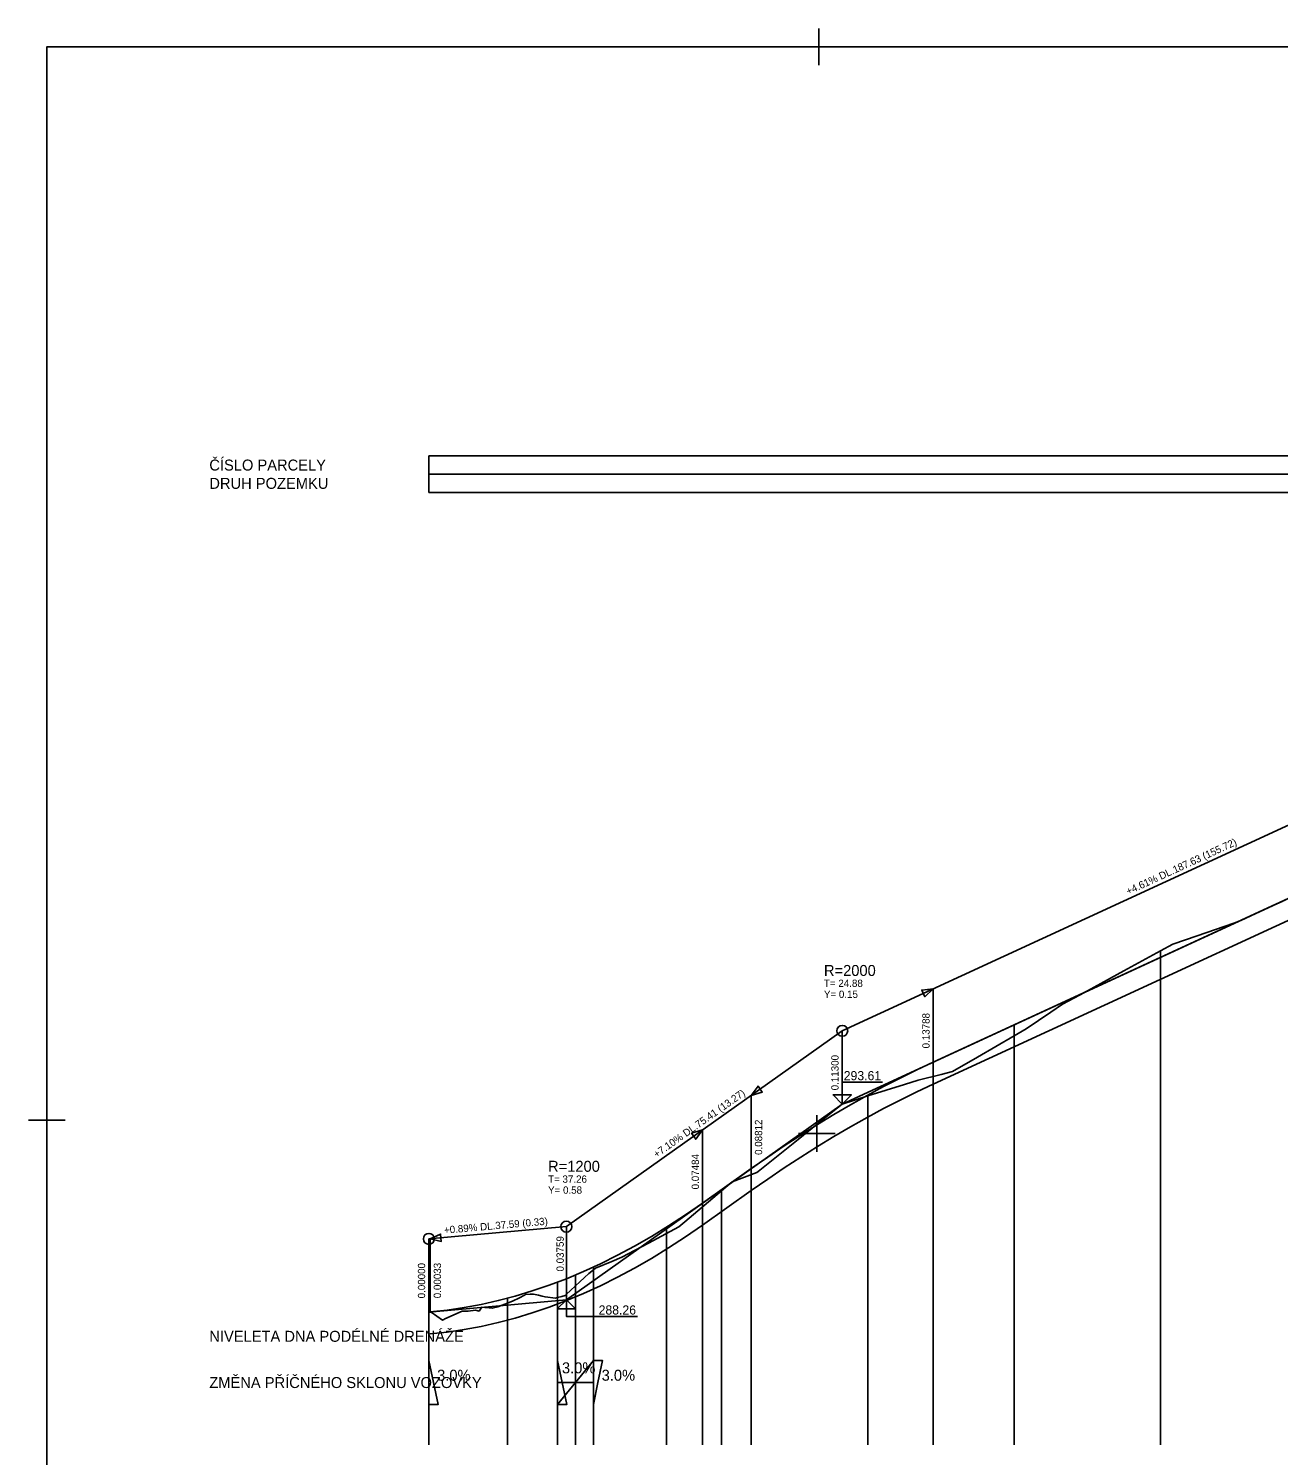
# Model space of a CAD drawing. Extents: x -39 to 1232, y -119 to 485.
# Drawn here: x -39.4 to 302.2, y 95.1 to 485.1 of the extents above; entities that cross this region are included whole.
import ezdxf

# ---------------------------------------------------------------- set-up
doc = ezdxf.new("R2010")
doc.units = 0
for name, color, linetype in [('KOTA', 7, 'Continuous'), ('NOVY_STAV', 7, 'Continuous'), ('NS_OBLOUK', 7, 'Continuous'), ('PRIKOPY', 7, 'Continuous'), ('ramecek', 7, 'Continuous'), ('REZY_PO', 7, 'Continuous'), ('SESTAVY_REZU_PO', 7, 'Continuous'), ('SKLONOVE_POMERY', 7, 'Continuous'), ('SKLONOVE_POMERY_PROPOJENI', 7, 'Continuous'), ('SVK_STAT', 7, 'Continuous'), ('TABULKY', 7, 'Continuous')]:
    doc.layers.add(name, color=color, linetype=linetype)

msp = doc.modelspace()

# ---------------------------------------------------------------- linework, layer by layer
for p, q in [((176.58, 485.08), (176.58, 475.08)), ((176.58, 485.08), (176.58, 475.08)), ((176.58, 485.08), (176.58, 475.08)), ((176.58, 485.08), (176.58, 475.08)), ((176.58, 485.08), (176.58, 475.08)), ((176.58, 485.08), (176.58, 475.08)), ((176.58, 485.08), (176.58, 475.08)), ((176.58, 485.08), (176.58, 475.08)), ((176.58, 485.08), (176.58, 475.08)), ((176.58, 485.08), (176.58, 475.08)), ((176.58, 485.08), (176.58, 475.08)), ((176.58, 485.08), (176.58, 475.08)), ((176.58, 485.08), (176.58, 475.08)), ((176.58, 485.08), (176.58, 475.08)), ((176.58, 485.08), (176.58, 475.08)), ((176.58, 485.08), (176.58, 475.08)), ((176.58, 485.08), (176.58, 475.08)), ((176.58, 485.08), (176.58, 475.08)), ((176.58, 485.08), (176.58, 475.08)), ((176.58, 485.08), (176.58, 475.08)), ((176.58, 485.08), (176.58, 475.08)), ((176.58, 485.08), (176.58, 475.08)), ((176.58, 485.08), (176.58, 475.08)), ((176.58, 485.08), (176.58, 475.08)), ((176.58, 485.08), (176.58, 475.08)), ((176.58, 485.08), (176.58, 475.08)), ((176.58, 485.08), (176.58, 475.08)), ((176.58, 485.08), (176.58, 475.08)), ((176.58, 485.08), (176.58, 475.08)), ((176.58, 485.08), (176.58, 475.08)), ((181.58, 480.08), (171.58, 480.08)), ((181.58, 480.08), (171.58, 480.08)), ((181.58, 480.08), (171.58, 480.08)), ((181.58, 480.08), (171.58, 480.08)), ((181.58, 480.08), (171.58, 480.08)), ((181.58, 480.08), (171.58, 480.08)), ((181.58, 480.08), (171.58, 480.08)), ((181.58, 480.08), (171.58, 480.08)), ((181.58, 480.08), (171.58, 480.08)), ((181.58, 480.08), (171.58, 480.08)), ((181.58, 480.08), (171.58, 480.08)), ((181.58, 480.08), (171.58, 480.08)), ((181.58, 480.08), (171.58, 480.08)), ((181.58, 480.08), (171.58, 480.08)), ((181.58, 480.08), (171.58, 480.08)), ((181.58, 480.08), (171.58, 480.08)), ((181.58, 480.08), (171.58, 480.08)), ((181.58, 480.08), (171.58, 480.08)), ((181.58, 480.08), (171.58, 480.08)), ((181.58, 480.08), (171.58, 480.08)), ((181.58, 480.08), (171.58, 480.08)), ((181.58, 480.08), (171.58, 480.08)), ((181.58, 480.08), (171.58, 480.08)), ((181.58, 480.08), (171.58, 480.08)), ((181.58, 480.08), (171.58, 480.08)), ((181.58, 480.08), (171.58, 480.08)), ((181.58, 480.08), (171.58, 480.08)), ((181.58, 480.08), (171.58, 480.08)), ((181.58, 480.08), (171.58, 480.08)), ((181.58, 480.08), (171.58, 480.08)), ((-34.42, 191.71), (-34.42, 181.71)), ((-34.42, 191.71), (-34.42, 181.71)), ((-34.42, 191.71), (-34.42, 181.71)), ((-34.42, 191.71), (-34.42, 181.71)), ((-34.42, 191.71), (-34.42, 181.71)), ((-34.42, 191.71), (-34.42, 181.71)), ((-34.42, 191.71), (-34.42, 181.71)), ((-34.42, 191.71), (-34.42, 181.71)), ((-34.42, 191.71), (-34.42, 181.71)), ((-34.42, 191.71), (-34.42, 181.71)), ((-34.42, 191.71), (-34.42, 181.71)), ((-34.42, 191.71), (-34.42, 181.71)), ((-34.42, 191.71), (-34.42, 181.71)), ((-34.42, 191.71), (-34.42, 181.71)), ((-34.42, 191.71), (-34.42, 181.71)), ((-34.42, 191.71), (-34.42, 181.71)), ((-34.42, 191.71), (-34.42, 181.71)), ((-34.42, 191.71), (-34.42, 181.71)), ((-34.42, 191.71), (-34.42, 181.71)), ((-34.42, 191.71), (-34.42, 181.71)), ((-34.42, 191.71), (-34.42, 181.71)), ((-34.42, 191.71), (-34.42, 181.71)), ((-34.42, 191.71), (-34.42, 181.71)), ((-34.42, 191.71), (-34.42, 181.71)), ((-34.42, 191.71), (-34.42, 181.71)), ((-34.42, 191.71), (-34.42, 181.71)), ((-34.42, 191.71), (-34.42, 181.71)), ((-34.42, 191.71), (-34.42, 181.71)), ((-34.42, 191.71), (-34.42, 181.71)), ((-34.42, 191.71), (-34.42, 181.71)), ((176.08, 188.08), (176.08, 178.08)), ((176.08, 188.08), (176.08, 178.08)), ((176.08, 188.08), (176.08, 178.08)), ((176.08, 188.08), (176.08, 178.08)), ((176.08, 188.08), (176.08, 178.08)), ((176.08, 188.08), (176.08, 178.08)), ((176.08, 188.08), (176.08, 178.08)), ((176.08, 188.08), (176.08, 178.08)), ((176.08, 188.08), (176.08, 178.08)), ((176.08, 188.08), (176.08, 178.08)), ((176.08, 188.08), (176.08, 178.08)), ((176.08, 188.08), (176.08, 178.08)), ((176.08, 188.08), (176.08, 178.08)), ((176.08, 188.08), (176.08, 178.08)), ((176.08, 188.08), (176.08, 178.08)), ((176.08, 188.08), (176.08, 178.08)), ((176.08, 188.08), (176.08, 178.08)), ((176.08, 188.08), (176.08, 178.08)), ((176.08, 188.08), (176.08, 178.08)), ((176.08, 188.08), (176.08, 178.08)), ((-29.42, 186.71), (-39.42, 186.71)), ((-29.42, 186.71), (-39.42, 186.71)), ((-29.42, 186.71), (-39.42, 186.71)), ((-29.42, 186.71), (-39.42, 186.71)), ((-29.42, 186.71), (-39.42, 186.71)), ((-29.42, 186.71), (-39.42, 186.71)), ((-29.42, 186.71), (-39.42, 186.71)), ((-29.42, 186.71), (-39.42, 186.71)), ((-29.42, 186.71), (-39.42, 186.71)), ((-29.42, 186.71), (-39.42, 186.71)), ((-29.42, 186.71), (-39.42, 186.71)), ((-29.42, 186.71), (-39.42, 186.71)), ((-29.42, 186.71), (-39.42, 186.71)), ((-29.42, 186.71), (-39.42, 186.71)), ((-29.42, 186.71), (-39.42, 186.71)), ((-29.42, 186.71), (-39.42, 186.71)), ((-29.42, 186.71), (-39.42, 186.71)), ((-29.42, 186.71), (-39.42, 186.71)), ((-29.42, 186.71), (-39.42, 186.71)), ((-29.42, 186.71), (-39.42, 186.71)), ((-29.42, 186.71), (-39.42, 186.71)), ((-29.42, 186.71), (-39.42, 186.71)), ((-29.42, 186.71), (-39.42, 186.71)), ((-29.42, 186.71), (-39.42, 186.71)), ((-29.42, 186.71), (-39.42, 186.71)), ((-29.42, 186.71), (-39.42, 186.71)), ((-29.42, 186.71), (-39.42, 186.71)), ((-29.42, 186.71), (-39.42, 186.71)), ((-29.42, 186.71), (-39.42, 186.71)), ((-29.42, 186.71), (-39.42, 186.71)), ((181.08, 183.08), (171.08, 183.08)), ((181.08, 183.08), (171.08, 183.08)), ((181.08, 183.08), (171.08, 183.08)), ((181.08, 183.08), (171.08, 183.08)), ((181.08, 183.08), (171.08, 183.08)), ((181.08, 183.08), (171.08, 183.08)), ((181.08, 183.08), (171.08, 183.08)), ((181.08, 183.08), (171.08, 183.08)), ((181.08, 183.08), (171.08, 183.08)), ((181.08, 183.08), (171.08, 183.08)), ((181.08, 183.08), (171.08, 183.08)), ((181.08, 183.08), (171.08, 183.08)), ((181.08, 183.08), (171.08, 183.08)), ((181.08, 183.08), (171.08, 183.08)), ((181.08, 183.08), (171.08, 183.08)), ((181.08, 183.08), (171.08, 183.08)), ((181.08, 183.08), (171.08, 183.08)), ((181.08, 183.08), (171.08, 183.08)), ((181.08, 183.08), (171.08, 183.08)), ((181.08, 183.08), (171.08, 183.08))]:
    msp.add_line(p, q)
at = {"layer": 'KOTA'}
for points in [[(183, 193.63), (180.5, 193.63), (183, 191.13), (183, 197.13), (194, 197.13)], [(183, 191.13), (183, 191.13), (185.5, 193.63), (183, 193.63)], [(107.59, 135.11), (105.09, 135.11), (107.59, 137.61), (107.59, 133.09), (127, 133.09)], [(107.59, 137.61), (107.59, 137.61), (110.09, 135.11), (107.59, 135.11)]]:
    msp.add_lwpolyline(points, dxfattribs=at)
at = {"layer": 'NOVY_STAV'}
for points in [[(70, 134.27), (107.59, 137.61), (183, 191.13), (370.63, 277.59), (464.64, 307.71), (524.44, 265.53), (860.29, 310.5), (1100.08, 191.45), (1135.72, 163.43), (1165.19, 163.09)], [(183, 211.13), (370.63, 297.59)], [(70, 134.27), (70.33, 134.3), (74.99, 134.81), (79.64, 135.49), (84.3, 136.36), (88.96, 137.4), (93.61, 138.63), (98.27, 140.04), (102.93, 141.62), (107.59, 143.39), (112.24, 145.34), (116.9, 147.47), (121.56, 149.78), (126.21, 152.27), (130.87, 154.95), (135.53, 157.8), (140.18, 160.83), (144.84, 164.05), (158.12, 173.47), (162.64, 176.63), (167.16, 179.68), (171.69, 182.64), (176.21, 185.49), (180.74, 188.24), (185.26, 190.89), (189.79, 193.43), (194.31, 195.88), (198.83, 198.22), (203.36, 200.46), (207.88, 202.59), (363.61, 274.35)], [(107.59, 157.61), (183, 211.13)], [(183, 191.13), (183, 211.13)], [(70, 154.27), (107.59, 157.61)], [(107.59, 137.61), (107.59, 157.61)], [(70, 134.27), (70, 154.27)]]:
    msp.add_lwpolyline(points, dxfattribs=at)
for centre in [(183, 211.13), (107.59, 157.61), (70, 154.27)]:
    msp.add_circle(centre, 1.5, dxfattribs=at)
at = {"layer": 'NS_OBLOUK'}
for points in [[(207.88, 222.59), (204.74, 222.25), (205.58, 220.43), (207.88, 222.59)], [(207.88, 202.59), (207.88, 222.59)], [(158.12, 193.47), (159.98, 196.02), (161.14, 194.39), (158.12, 193.47)], [(158.12, 173.47), (158.12, 193.47)], [(144.84, 184.05), (141.82, 183.13), (142.98, 181.5), (144.84, 184.05)], [(144.84, 164.05), (144.84, 184.05)], [(70.33, 154.3), (73.23, 155.57), (73.41, 153.57), (70.33, 154.3)], [(70.33, 134.3), (70.33, 154.3)]]:
    msp.add_lwpolyline(points, dxfattribs=at)
at = {"layer": 'PRIKOPY'}
msp.add_lwpolyline([(70, 128.27), (70.33, 128.3), (74.99, 128.81), (79.64, 129.49), (84.3, 130.36), (88.96, 131.4), (93.61, 132.63), (98.27, 134.04), (102.93, 135.62), (107.59, 137.39), (112.24, 139.34), (116.9, 141.47), (121.56, 143.78), (126.21, 146.27), (130.87, 148.95), (135.53, 151.8), (140.18, 154.83), (144.84, 158.05), (158.12, 167.47), (162.64, 170.63), (167.16, 173.68), (171.69, 176.64), (176.21, 179.49), (180.74, 182.24), (185.26, 184.89), (189.79, 187.43), (194.31, 189.88), (198.83, 192.22), (203.36, 194.46), (207.88, 196.59), (363.61, 268.35)], dxfattribs=at)
at = {"layer": 'ramecek'}
msp.add_lwpolyline([(-34.42, -113.92), (1226.58, -113.92), (1226.58, 480.08), (-34.42, 480.08)], close=True, dxfattribs=at)
at = {"layer": 'REZY_PO'}
msp.add_lwpolyline([(70, 134.27), (70.58, 134.22), (70.62, 134.21), (70.63, 134.2), (73.78, 132.09), (74.12, 132.21), (74.36, 132.4), (79.11, 134.53), (80, 134.5), (80.73, 134.47), (82.8, 134.82), (83.75, 134.52), (84.5, 135.61), (85.35, 135.5), (86.51, 135.38), (87.34, 135.33), (87.67, 135.41), (88.84, 135.74), (90, 136.12), (90.76, 136.39), (91.52, 136.69), (93.07, 137.35), (94.61, 138.09), (96.16, 138.92), (96.45, 139.09), (97.7, 139.14), (98.58, 139.19), (100, 138.85), (101.02, 138.61), (101.78, 138.39), (104.63, 138.1), (105.17, 138.23), (106.37, 138.52), (107.27, 138.75), (107.58, 139.06), (108.79, 140.22), (110, 141.36), (110.04, 141.4), (110.07, 141.43), (111.3, 142.57), (112.53, 143.68), (113.75, 144.77), (114.98, 145.82), (115.53, 146.29), (120, 148.11), (122.77, 149.23), (130, 153.11), (138.36, 157.58), (140, 158.97), (150, 167.41), (150, 167.41), (152.89, 169.85), (159.64, 172.44), (160, 172.73), (170, 180.73), (180, 188.73), (183, 191.13), (190, 193.33), (190, 193.33), (200, 196.49), (203.75, 197.67), (210, 199.21), (213.11, 199.98), (220, 203.97), (230, 209.76), (230, 209.76), (233.26, 211.65), (240, 216.21), (243.23, 218.39), (247.86, 220.92), (250, 222.09), (260, 227.56), (270, 233.03), (273.34, 234.85), (280, 237.14), (290, 240.59), (291.97, 241.26), (300, 244.99), (303.45, 246.6)], dxfattribs=at)
at = {"layer": 'SKLONOVE_POMERY'}
for points in [[(70, 109), (70, 121), (70, 121), (71.26, 115), (72.52, 109), (70, 109)], [(105.17, 109), (105.17, 121), (105.17, 121), (106.43, 115), (107.69, 109), (105.17, 109)], [(114.98, 109), (114.98, 121), (117.5, 121), (116.24, 115), (114.98, 109), (114.98, 109)]]:
    msp.add_lwpolyline(points, dxfattribs=at)
at = {"layer": 'SKLONOVE_POMERY_PROPOJENI'}
for points in [[(105.17, 109), (114.98, 121)], [(105.17, 115), (114.98, 115)]]:
    msp.add_lwpolyline(points, dxfattribs=at)
at = {"layer": 'SVK_STAT'}
for points in [[(270, 98), (270, 233.03)], [(230, 98), (230, 212.79)], [(207.88, 98), (207.88, 202.59)], [(190, 98), (190, 193.55)], [(158.12, 98), (158.12, 173.47)], [(150, 98), (150, 167.71)], [(144.84, 98), (144.84, 164.05)], [(134.98, 98), (134.98, 157.46)], [(110.07, 98), (110.07, 144.43)], [(114.98, 98), (114.98, 146.59)], [(105.17, 98), (105.17, 142.47)], [(91.52, 98), (91.52, 138.08)], [(70, 98), (70, 134.27)]]:
    msp.add_lwpolyline(points, dxfattribs=at)
at = {"layer": 'TABULKY'}
for points in [[(70, 358.27), (1165.19, 358.27), (1165.19, 368.27), (70, 368.27), (70, 358.27)], [(70, 363.27), (1165.19, 363.27)]]:
    msp.add_lwpolyline(points, dxfattribs=at)

# ---------------------------------------------------------------- texts
at = {"layer": 'KOTA'}
for s, p in [('293.61', (183.41, 197.63)), ('288.26', (116.41, 133.59))]:
    msp.add_text(s, height=2.5, dxfattribs=at).set_placement(p)
at = {"layer": 'NOVY_STAV'}
for s, rotation, p in [('+4.61% DL.187.63 (155.72)', 24.741, (261.15, 248.24)), (' 0.11300', 90, (182, 194.13)), ('+7.10% DL.75.41 (13.27)', 35.3617, (132.26, 176.34)), ('+0.89% DL.37.59 (0.33)', 5.0691, (74.24, 155.65)), (' 0.03759', 90, (106.89, 144.61)), (' 0.00000', 90, (69, 137.27))]:
    msp.add_text(s, height=2, rotation=rotation, dxfattribs=at).set_placement(p)
at = {"layer": 'NS_OBLOUK'}
for s, height, p in [('R=2000', 3, (178, 226.13)), ('T= 24.88', 2, (178, 223.13)), ('Y= 0.15', 2, (178, 220.13)), ('R=1200', 3, (102.59, 172.61)), ('T= 37.26', 2, (102.59, 169.61)), ('Y= 0.58', 2, (102.59, 166.61))]:
    msp.add_text(s, height=height, dxfattribs=at).set_placement(p)
for s, p in [(' 0.13788', (206.88, 205.59)), (' 0.08812', (161.12, 176.47)), (' 0.07484', (143.84, 167.05)), (' 0.00033', (73.33, 137.3))]:
    msp.add_text(s, height=2, rotation=90, dxfattribs=at).set_placement(p)
at = {"layer": 'SESTAVY_REZU_PO'}
for s, p in [('NIVELETA DNA PODÉLNÉ DRENÁŽE', (10, 126.14)), ('ZMĚNA PŘÍČNÉHO SKLONU VOZOVKY', (10, 113.5))]:
    msp.add_text(s, height=3, dxfattribs=at).set_placement(p)
at = {"layer": 'SKLONOVE_POMERY'}
for p in [(72.26, 115.5), (106.39, 117.52), (117.24, 115.5)]:
    msp.add_text('3.0%', height=3, dxfattribs=at).set_placement(p)
at = {"layer": 'TABULKY'}
for s, p in [('ČÍSLO PARCELY', (10, 364.27)), ('DRUH POZEMKU', (10, 359.27))]:
    msp.add_text(s, height=3, dxfattribs=at).set_placement(p)

doc.saveas('drawing.dxf')
